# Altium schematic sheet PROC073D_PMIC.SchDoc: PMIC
size 431 x 279 mm; Date: Not shown in title block; ApprovedBy: Not shown in title block; CheckedBy: Not shown in title block; Author: Not shown in title block; CompanyName: Not shown in title block; DrawnBy: Charles F. Oladimeji; Engineer: Not shown in title block; Organization: Not shown in title block; Address1: Not shown in title block; Address2: Not shown in title block; Address3: Not shown in title block; Address4: Not shown in title block; DocumentNumber: 3; Revision: Use project parameter SCH_Rev; SheetNumber: 3; SheetTotal: 13; PageSetup: Record=PageOptions¦CenterHorizontal=True¦CenterVertical=True¦PrintScale=1.00¦XCorrection=1.00¦YCorrection=1.00¦PrintKind=0¦BorderSize=5000000¦LeftOffset=0¦BottomOffset=0¦Orientation=2¦PaperLength=1000¦PaperWidth=1000¦Scale=100¦PaperSource=15¦PrintQuality=600¦MediaType=1¦DitherType=10¦PaperKind=Letter¦PrintScaleMode=1
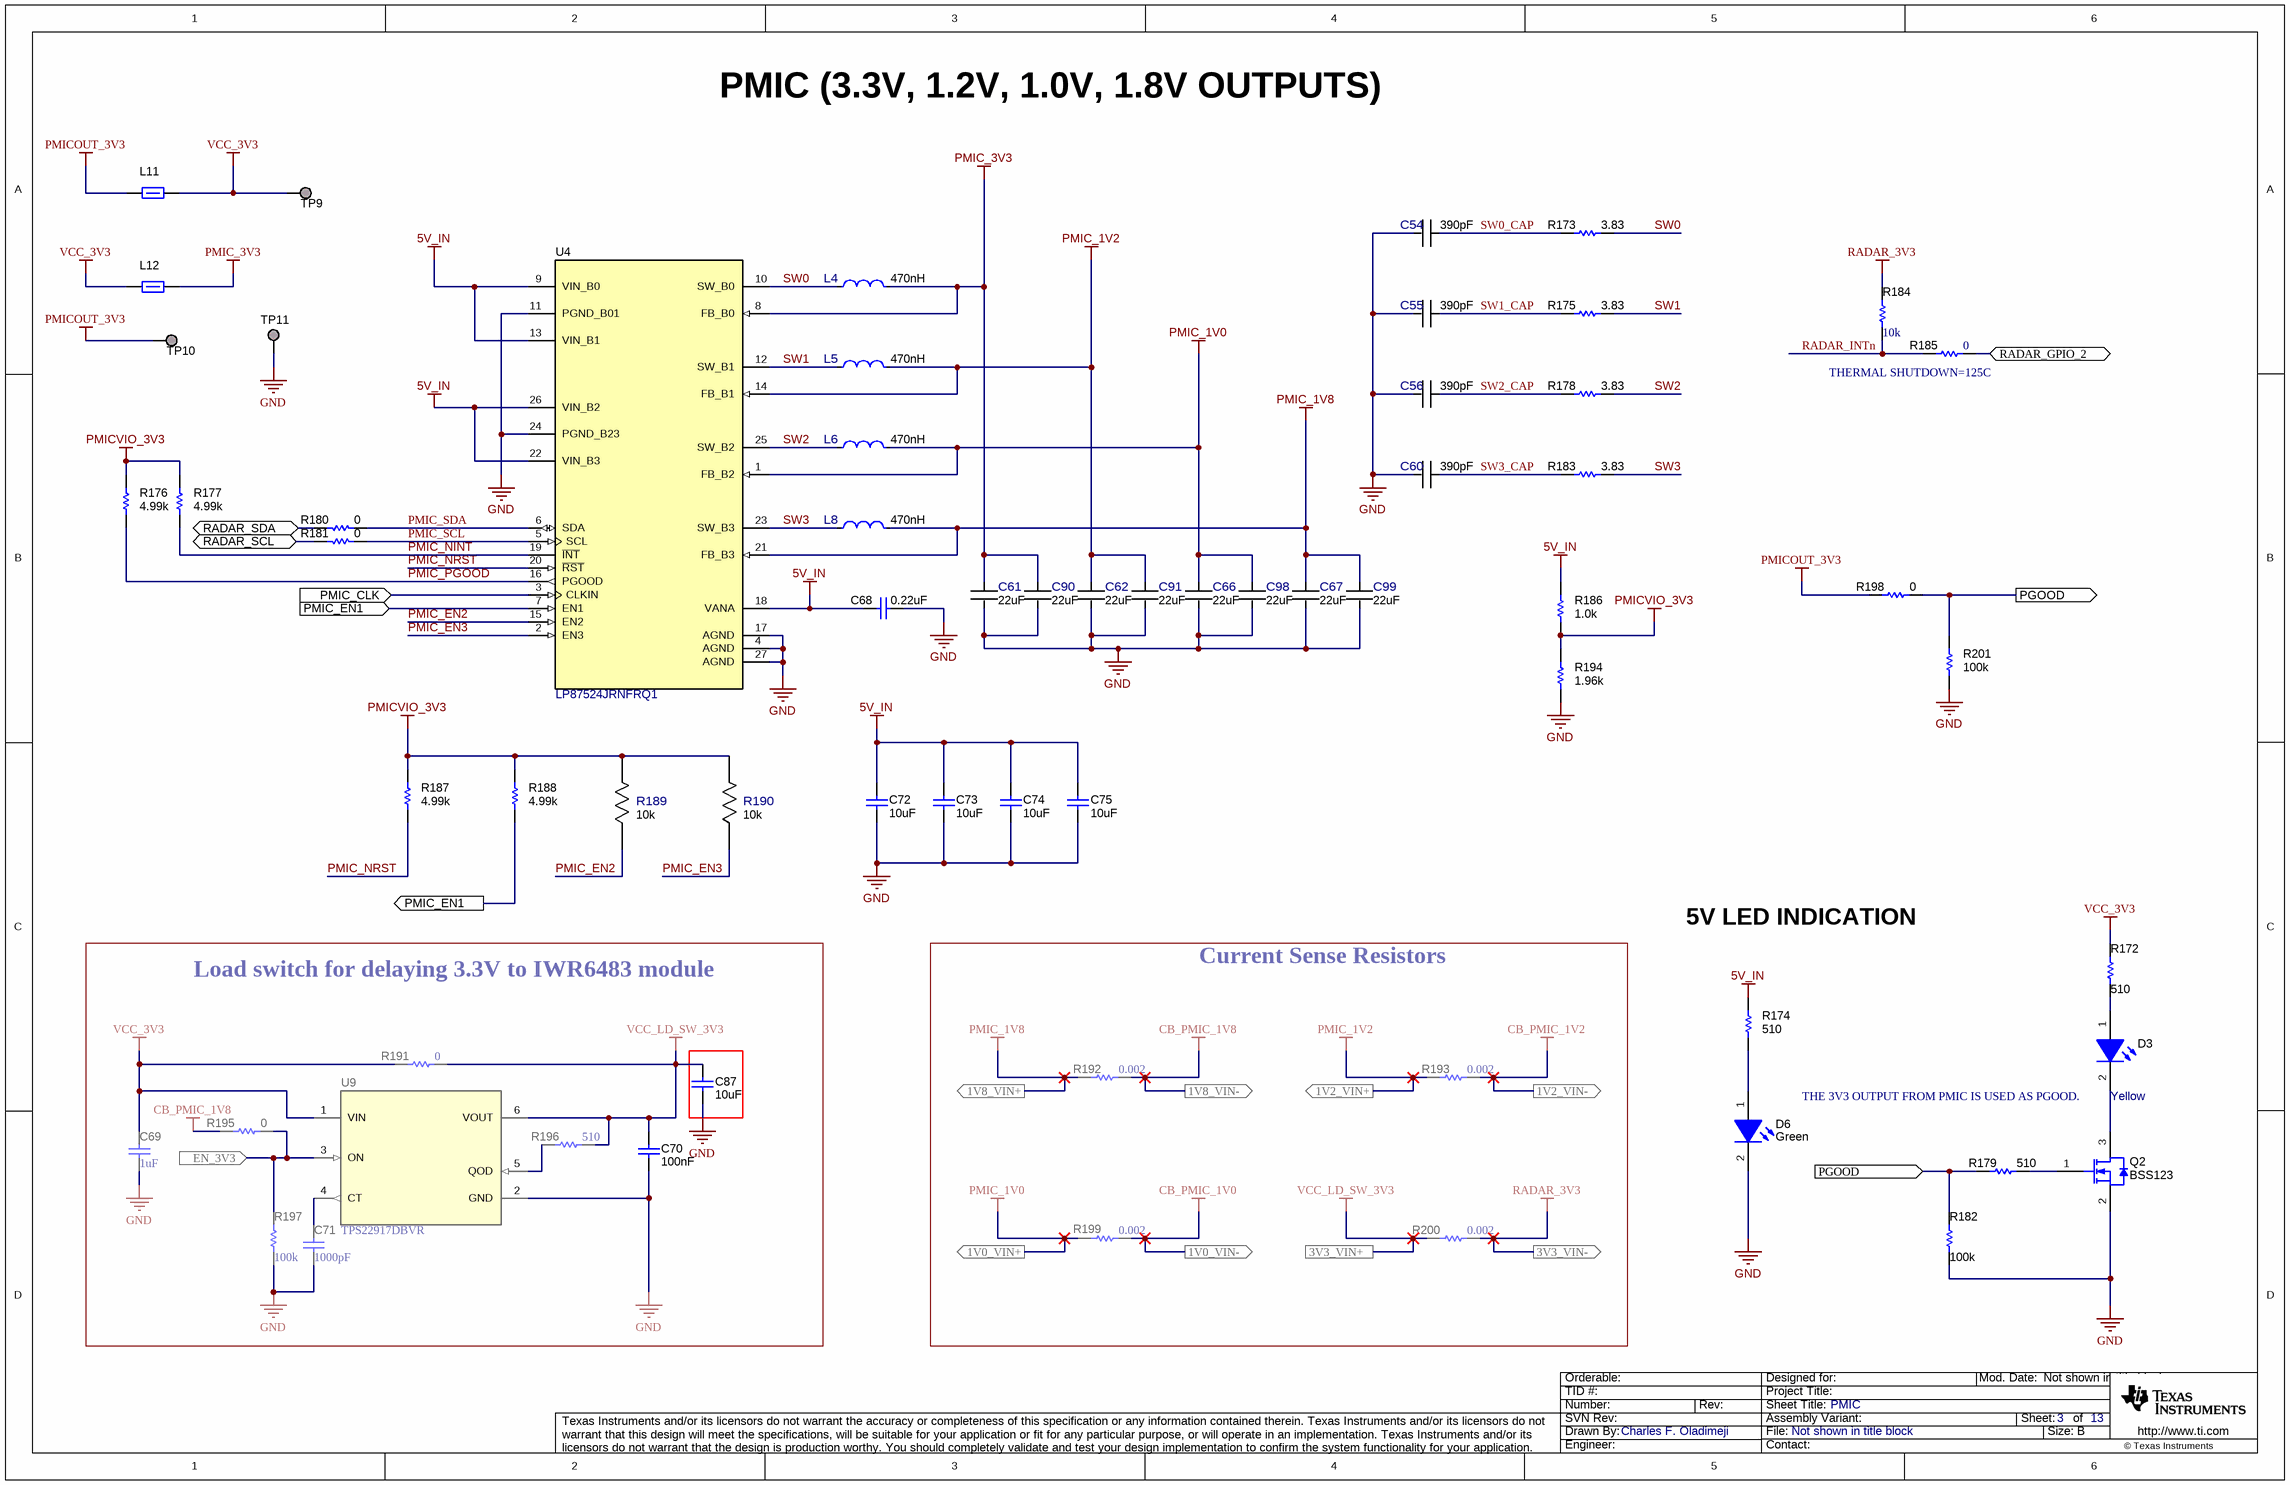
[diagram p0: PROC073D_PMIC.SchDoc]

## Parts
C54  Cap_F: 390pF  [FP-TMK063CG391JT-F_0201 (0603 Metric)-IPC_C]  (hidden comment: TMK063CG391JT-F)
C55  Cap_F: 390pF  [FP-TMK063CG391JT-F_0201 (0603 Metric)-IPC_C]  (hidden comment: TMK063CG391JT-F)
C56  Cap_F: 390pF  [FP-TMK063CG391JT-F_0201 (0603 Metric)-IPC_C]  (hidden comment: TMK063CG391JT-F)
C60  Cap_F: 390pF  [FP-TMK063CG391JT-F_0201 (0603 Metric)-IPC_C]  (hidden comment: TMK063CG391JT-F)
C61  Cap_F: 22uF  [FP-CL05A226MQ5N6J8_0402 (1005 Metric)-IPC_C]  (hidden comment: CL05A226MQ5N6J8)
C62  Cap_F: 22uF  [FP-CL05A226MQ5N6J8_0402 (1005 Metric)-IPC_C]  (hidden comment: CL05A226MQ5N6J8)
C66  Cap_F: 22uF  [FP-CL05A226MQ5N6J8_0402 (1005 Metric)-IPC_C]  (hidden comment: CL05A226MQ5N6J8)
C67  Cap_F: 22uF  [FP-CL05A226MQ5N6J8_0402 (1005 Metric)-IPC_C]  (hidden comment: CL05A226MQ5N6J8)
C68  value 0.22uF  [0201_033L]  (hidden comment: LMK063BJ224MP-F)
C69  ValueDisplayed: 1uF  [0603]  (hidden comment: CL10B105KQ8NNNC)
C70  Cap_F: 100nF  [0603]  (hidden comment: C0603C104J5RACTU)
C71  ValueDisplayed: 1000pF  [0402]  (hidden comment: CGA2B3X7S2A102K050BB)
C72  value 10uF  [0402_070]  (hidden comment: CL05A106MP5NUNC)
C73  value 10uF  [0402_070]  (hidden comment: CL05A106MP5NUNC)
C74  value 10uF  [0402_070]  (hidden comment: CL05A106MP5NUNC)
C75  value 10uF  [0402_070]  (hidden comment: CL05A106MP5NUNC)
C87  ValueDisplayed: 10uF  [0603S]  (hidden comment: GRT188R61A106KE13D)
C90  Cap_F: 22uF  [FP-CL05A226MQ5N6J8_0402 (1005 Metric)-IPC_C]  (hidden comment: CL05A226MQ5N6J8)
C91  Cap_F: 22uF  [FP-CL05A226MQ5N6J8_0402 (1005 Metric)-IPC_C]  (hidden comment: CL05A226MQ5N6J8)
C98  Cap_F: 22uF  [FP-CL05A226MQ5N6J8_0402 (1005 Metric)-IPC_C]  (hidden comment: CL05A226MQ5N6J8)
C99  Cap_F: 22uF  [FP-CL05A226MQ5N6J8_0402 (1005 Metric)-IPC_C]  (hidden comment: CL05A226MQ5N6J8)
D3  value Yellow  [TLMx1000_Yellow]  (hidden comment: TLMY1000-GS08)
D6  Color: Green  [APHHS1005_Green]  (hidden comment: APHHS1005CGCK)
L4  Ind_H: 470nH  [FP-MCKK2012TR47M_0805 (2012 Metric)-IPC_C]  (hidden comment: MCKK2012TR47M)
L5  Ind_H: 470nH  [FP-MCKK2012TR47M_0805 (2012 Metric)-IPC_C]  (hidden comment: MCKK2012TR47M)
L6  Ind_H: 470nH  [FP-MCKK2012TR47M_0805 (2012 Metric)-IPC_C]  (hidden comment: MCKK2012TR47M)
L8  Ind_H: 470nH  [FP-MCKK2012TR47M_0805 (2012 Metric)-IPC_C]  (hidden comment: MCKK2012TR47M)
L11  BLM15PD300SZ1D  [0402L]  (value not drawn)
L12  BLM15PD300SZ1D  [0402L]  (value not drawn)
Q2  BSS123  [SOT-23]
R172  ValueDisplayed: 510  [0402L]  (hidden comment: ERJ-2GEJ511X)
R173  Res_ohm: 3.83  [FP-RC0402FR-073R83L_0402 (1005 Metric)-IPC_C]  (hidden comment: RC0402FR-073R83L)
R174  value 510  [0201L]  (hidden comment: RC0201JR-07510RL)
R175  Res_ohm: 3.83  [FP-RC0402FR-073R83L_0402 (1005 Metric)-IPC_C]  (hidden comment: RC0402FR-073R83L)
R176  value 4.99k  [0201L]  (hidden comment: RC0201FR-074K99L)
R177  value 4.99k  [0201L]  (hidden comment: RC0201FR-074K99L)
R178  Res_ohm: 3.83  [FP-RC0402FR-073R83L_0402 (1005 Metric)-IPC_C]  (hidden comment: RC0402FR-073R83L)
R179  ValueDisplayed: 510  [0402L]  (hidden comment: ERJ-2GEJ511X)
R180  Res_ohm: 0  [FP-RC0201JR-070RL_0201 (0603 Metric)-MFG]  (hidden comment: RC0201JR-070RL)
R181  Res_ohm: 0  [FP-RC0201JR-070RL_0201 (0603 Metric)-MFG]  (hidden comment: RC0201JR-070RL)
R182  ValueDisplayed: 100k  [0402L]  (hidden comment: CRCW0402100KFKED)
R183  Res_ohm: 3.83  [FP-RC0402FR-073R83L_0402 (1005 Metric)-IPC_C]  (hidden comment: RC0402FR-073R83L)
R184  value 10k  [0402]  (hidden comment: CRCW040210K0JNED)
R185  Res_ohm: 0  [0402]  (hidden comment: CRCW04020000Z0ED)
R186  value 1.0k  [0201L]  (hidden comment: RC0201JR-071KL)
R187  value 4.99k  [0201L]  (hidden comment: RC0201FR-074K99L)
R188  value 4.99k  [0201L]  (hidden comment: RC0201FR-074K99L)
R189  Res_ohm: 10k  [FP-RR0306P-103-D_0201-IPC_C]  (hidden comment: RR0306P-103-D)
R190  Res_ohm: 10k  [FP-RR0306P-103-D_0201-IPC_C]  (hidden comment: RR0306P-103-D)
R191  ValueDisplayed: 0  [0603]  (hidden comment: RCS06030000Z0EA)
R192  ValueDisplayed: 0.002  [1206]  (hidden comment: PMR18EZPFV2L00)
R193  ValueDisplayed: 0.002  [1206]  (hidden comment: PMR18EZPFV2L00)
R194  value 1.96k  [0201L]  (hidden comment: RC0201FR-071K96L)
R195  ValueDisplayed: 0  [0603]  (hidden comment: MCT06030Z0000ZP500)
R196  ValueDisplayed: 510  [0402]  (hidden comment: CRCW0402510RJNED)
R197  ValueDisplayed: 100k  [0402]  (hidden comment: ERJ-2RKF1003X)
R198  Res_ohm: 0  [FP-RC0201JR-070RL_0201 (0603 Metric)-MFG]  (hidden comment: RC0201JR-070RL)
R199  ValueDisplayed: 0.002  [1206]  (hidden comment: PMR18EZPFV2L00)
R200  ValueDisplayed: 0.002  [1206]  (hidden comment: PMR18EZPFV2L00)
R201  value 100k  [0201L]  (hidden comment: CRCW0201100KFKED)
TP9  TESTPOINT  [TP_25MIL-SMT]  (value not drawn)  (no BOM)
TP10  TESTPOINT  [TP_25MIL-SMT]  (value not drawn)  (no BOM)
TP11  TESTPOINT  [TP_VIA_060RND040]  (value not drawn)  (no BOM)
U4  LP87524JRNFRQ1  [RNF0026C]
U9  TPS22917DBVR  [DBV0006A_N]

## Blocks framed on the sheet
Load switch for delaying 3.3V to IWR6483 module: C69-C71 C87 R191 R195-R197 U9
Current Sense Resistors: R192 R193 R199 R200

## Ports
1V0_VIN+ (out), 1V0_VIN- (out), 1V2_VIN+ (out), 1V2_VIN- (out), 1V8_VIN+ (out), 1V8_VIN- (out), 3V3_VIN+, 3V3_VIN- (out), EN_3V3 (in), PGOOD (in), PGOOD (out), PMIC_CLK (in), PMIC_EN1 (in), PMIC_EN1 (out), RADAR_GPIO_2 (bidir), RADAR_SCL (bidir), RADAR_SDA (bidir)

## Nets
5V_IN: C68.1 C72.1 C73.1 C74.1 C75.1 R174.1 R186.2 U4.9(VIN_B0) U4.13(VIN_B1) U4.18(VANA) U4.22(VIN_B3) U4.26(VIN_B2)
CB_PMIC_1V0: R199.2 ; port 1V0_VIN-
CB_PMIC_1V2: R193.2 ; port 1V2_VIN-
CB_PMIC_1V8: R192.2 R195.1 ; port 1V8_VIN-
GND: C54.2 C55.2 C56.2 C60.2 C61.2 C62.2 C66.2 C67.2 C68.2 C69.2 C70.2 C71.2 C72.2 C73.2 C74.2 C75.2 C87.1 C90.2 C91.2 C98.2 C99.2 D6.2(K) Q2.2(S) R182.1 R194.1 R197.1 R201.1 TP11.1 U4.4(AGND) U4.11(PGND_B01) U4.17(AGND) U4.24(PGND_B23) U4.27(AGND) U9.2(GND)
PMIC_1V0: C66.1 C98.1 L6.1 R199.1 U4.1(FB_B2) ; port 1V0_VIN+
PMIC_1V2: C62.1 C91.1 L5.1 R193.1 U4.14(FB_B1) ; port 1V2_VIN+
PMIC_1V8: C67.1 C99.1 L8.1 R192.1 U4.21(FB_B3) ; port 1V8_VIN+
PMIC_3V3: C61.1 C90.1 L4.1 L12.2 U4.8(FB_B0)
PMICOUT_3V3: L11.1 R198.2 TP10.1
PMICVIO_3V3: R176.2 R177.2 R186.1 R187.2 R188.2 R189.2 R190.2 R194.2
RADAR_3V3: R184.2 R200.2 ; port 3V3_VIN-
VCC_3V3: C69.1 L11.2 L12.1 R172.2 R191.1 TP9.1 U9.1(VIN)
VCC_LD_SW_3V3: C70.1 C87.2 R191.2 R196.1 R200.1 U9.6(VOUT) ; port 3V3_VIN+
EN_3V3: R195.2 R197.2 U9.3(ON) ; port EN_3V3
PGOOD: R179.1 R182.2 R198.1 R201.2 ; port PGOOD
PMIC_CLK: U4.3(CLKIN) ; port PMIC_CLK
PMIC_EN1: R188.1 U4.7(EN1) ; port PMIC_EN1
PMIC_EN2: R189.1 U4.15(EN2)
PMIC_EN3: R190.1 U4.2(EN3)
PMIC_NINT: R177.1 U4.19(~{INT})
PMIC_NRST: R187.1 U4.20(~{RST})
PMIC_PGOOD: R176.1 U4.16(PGOOD)
PMIC_SCL: R181.2 U4.5(SCL)
PMIC_SDA: R180.2 U4.6(SDA)
RADAR_GPIO_2: R185.2 ; port RADAR_GPIO_2
RADAR_INTn: R184.1 R185.1
RADAR_SCL: R181.1 ; port RADAR_SCL
RADAR_SDA: R180.1 ; port RADAR_SDA
SW0: L4.2 R173.2 U4.10(SW_B0)
SW0_CAP: C54.1 R173.1
SW1: L5.2 R175.2 U4.12(SW_B1)
SW1_CAP: C55.1 R175.1
SW2: L6.2 R178.2 U4.25(SW_B2)
SW2_CAP: C56.1 R178.1
SW3: L8.2 R183.2 U4.23(SW_B3)
SW3_CAP: C60.1 R183.1
NetC71_1: C71.1 U9.4(CT)
NetD3_1: D3.1(A) R172.1
NetD3_2: D3.2(K) Q2.3(D)
NetD6_1: D6.1(A) R174.2
NetQ2_1: Q2.1(G) R179.2
NetR196_2: R196.2 U9.5(QOD)

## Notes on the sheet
- PMIC (3.3V, 1.2V, 1.0V, 1.8V OUTPUTS)
- (near R185) THERMAL SHUTDOWN=125C
- 5V LED INDICATION
- THE 3V3 OUTPUT FROM PMIC IS USED AS PGOOD.

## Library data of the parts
C54-C56 C60 = CMP-0086438-1: CAP CER 390PF 25V C0G/NP0 0201; Manufacturer: Taiyo Yuden; AEC Qualified: No; SizeZ_mm: 0.33mm; Symbol Name: SYM-TMK063CG391JT-F; TempCo: 30ppm/°C; Tolerance_%: 5%
C61 C62 C66 C67 C90 C91 C98 C99 = CMP-0086447-1: CAP CER 22UF 6.3V X5R 0402; Manufacturer: Samsung Electro-Mechanics; AEC Qualified: No; SizeZ_mm: 0.55mm; Symbol Name: SYM-CL05A226MQ5N6J8; TempCo: 15%; Tolerance_%: 20%
C68 = CMP-0009781-1: CAP, CERM, 0.22 uF, 10 V, +/- 20%, X5R, 0201; Manufacturer: Taiyo Yuden; AEC Category: Q200; AEC Qualified: N; Cap_Case: 0201; Cap_F: 220nF; SizeArea_mm2: 0.18; SizeAreaWB_mm2: 2.08; SizeX_mm: 0.6; SizeY_mm: 0.3; SizeZ_mm: 0.33; TaMax_C: 85°C; TaMin_C: -55°C; U/M: EA; Value1: Unknown; Value2: 10V
C69 = CMP-0007111-4: CAP, CERM, 1 uF, 6.3 V, +/- 10%, X7R, 0603; Manufacturer: Samsung Electro-Mechanics; TaMin_C: -55°C; Polarized: N; SizeAreaWB_mm2: 4.68; Value1: Unknown; U/M: EA; Value: 1uF; TaMax_C: 125°C; SizeZ_mm: 1; SizeX_mm: 1.6; SizeY_mm: 0.8; Value2: 6.3V; SizeArea_mm2: 1.28; CompType: Capacitor; Cap_F: 1µF; AEC Category: Q200
C70 = CMP-0006858-4: CAP, CERM, 0.1 uF, 50 V, +/- 5%, X7R, 0603; Manufacturer: Kemet; TaMin_C: -55°C; Polarized: N; SizeAreaWB_mm2: 4.68; Value1: Unknown; U/M: EA; Value: 0.1uF; TaMax_C: 125°C; SizeZ_mm: 1; SizeX_mm: 1.6; SizeY_mm: 0.8; Value2: 50V; SizeArea_mm2: 1.28; AEC Category: Q200
C71 = CMP-0006332-2: CAP, CERM, 1000 pF, 100 V, +/- 10%, X7S, AEC-Q200 Grade 1, 0402; Manufacturer: TDK; TaMin_C: -55°C; ESR_ohm: 2.71151; Polarized: N; SizeAreaWB_mm2: 3; Value1: 2.71151 ohm; U/M: EA; Value: 1000pF; TaMax_C: 125°C; SizeZ_mm: 0.6; SizeX_mm: 1; SizeY_mm: 0.5; Value2: 100V; AEC Qualified: Y; Cap_F: 1nF; IRMS_A: 2.64589dA; AEC Category: Q200
C72-C75 = CMP-0006339-4: CAP, CERM, 10 uF, 10 V, +/- 20%, X5R, 0402; Manufacturer: Samsung Electro-Mechanics; AEC Category: Q200; AEC Qualified: N; Cap_Case: 0402; Cap_F: 10µF; SizeArea_mm2: 0.5; SizeAreaWB_mm2: 3; SizeX_mm: 1; SizeZ_mm: 0.6; TaMax_C: 85°C; TaMin_C: -55°C; U/M: EA; Value1: Unknown; Value2: 10V
C87 = CMP-0007497-5: CAP, CERM, 10 uF, 10 V, +/- 10%, X5R, 0603; Manufacturer: MuRata; Polarized: N; Value: 10uF; U/M: EA; Cap_F: 10µF; Tolerance_%: 20%; Value1: Unknown; VDC_V: 10V; TempCo: X7R; TaMin_C: -55°C; TaMax_C: 125°C; Cap_Case: 0603; SizeArea_mm2: 1.28; SizeAreaWB_mm2: 4.68; SizeX_mm: 1.6; SizeY_mm: 0.8; SizeZ_mm: 1; AEC Category: Q200
D3 = CMP-0078196-2: LED, Yellow, SMD; Manufacturer: Vishay-Semiconductor; Tjmax_C: 120°C; SizeAreaWB_mm2: 4.68; Vr_V: 6V; Power_TotalModule: 40mW; Angle: 160; SizeArea_mm2: 1.28; Ir_A: 10µA; SizeZ_mm: 0.65; Io_A: 2mA; Vf_V: 1.8V; SizeY_mm: 0.8; Value1: .04W; SizeX_mm: 1.6; Type: AlInGaP
D6 = CMP-0067682-2: LED, Green, SMD; Manufacturer: Kingbright; Angle: 120.0; Power_TotalModule: 75mW; SizeZ_mm: 0.6; Vf_V: 2.1V; Vr_V: 5V; Io_A: 20mA; Ir_A: 10µA; SizeArea_mm2: 0.5; SizeAreaWB_mm2: 3.0; SizeX_mm: 1.0; Tjmax_C: 85°C; Value1: 0.075W
L4-L6 L8 = CMP-0087178-1: FIXED IND 470NH 4.5A 39 MOHM SMD; Manufacturer: Taiyo Yuden; AEC Qualified: No; DCR_ohm: 0.032; Irms: 3.1A; Material: Metal; SizeZ_mm: 1mm; Symbol Name: SYM-MCKK2012TR47M
L11 L12 = CMP-0078934-1: Inductor, Ferrite Bead, Ferrite, 2.2 A, 0.035 ohm, AEC-Q200 Grade 1, SMD; Manufacturer: MuRata; AEC Category: Q200; AEC Grade: 1; AEC Qualified: Y; DCR_ohm: 0.035; Imax_A: 2.2A; SizeArea_mm2: 0.5; SizeAreaWB_mm2: 3; SizeZ_mm: 0.6
Q2 = CMP-0000947-2: MOSFET, N-CH, 100 V, 0.17 A, SOT-23; Alternate Manufacturer: None; Manufacturer: Fairchild Semiconductor; SizeZ_mm: 1.1; ChType: N; Value2: 1.8 nC; Value1: 1; VdsMax_V: 100V; SizeX_mm: 2.5; SizeY_mm: 3; Vgs_V: 20V; Value: 100V; Rdson45_ohm: 10; SizeArea_mm2: 7.5; AEC Category: Q101; IdsMax_A: 1.7dA; SizeAreaWB_mm2: 14; U/M: EA; QgTyp_nC: 1.8
R172 R179 = CMP-0078212-1: RES, 510, 5%, 0.1 W, AEC-Q200 Grade 0, 0402; Manufacturer: Panasonic; Value_Code: 510R; SizeArea_mm2: 0.5; AEC Qualified: Y; AEC Category: Q200; Value: 510; SizeZ_mm: 0.6; EIA_Code: E24; TempCo: 200 ppm/C; AEC Grade: 0; Power_W: 100mW; VDC_V: 50V; Value2: 0.1W; U/M: EA; SizeX_mm: 1
R173 R175 R178 R183 = CMP-0086444-2: RES Thick Film SMD 3.83Ω 1% 1/16W 0402 200ppm/°C; Manufacturer: Yageo; AEC Qualified: No; Power_W: 63mW; VDC_V: 50V; SizeZ_mm: 0.4mm
R174 = CMP-0027137-1: RES, 510, 5%, 0.05 W, 0201; Manufacturer: Yageo America; AEC Category: Q200; AEC Qualified: N; EIA_Code: E24; Power_W: 50mW; SizeArea_mm2: 0.18; SizeX_mm: 0.6; SizeY_mm: 0.3; SizeZ_mm: 0.26; TempCo: 200 ppm/C; U/M: EA; Value2: 0.05W; Value_Code: 510R; VDC_V: 25V
R176 R177 R187 R188 = CMP-0027745-1: RES, 4.99 k, 1%, 0.05 W, 0201; Manufacturer: Yageo America; AEC Category: Q200; AEC Qualified: N; EIA_Code: E96; Power_W: 50mW; SizeArea_mm2: 0.18; SizeX_mm: 0.6; SizeY_mm: 0.3; SizeZ_mm: 0.26; TempCo: 200 ppm/C; U/M: EA; Value2: 0.05W; Value_Code: 4k99; VDC_V: 25V
R180 R181 R198 = CMP-0086442-2: RES SMD 0 OHM JUMPER 1/20W 0201; Manufacturer: Yageo; AEC Qualified: No; Power_W: 50mW; SizeZ_mm: 0.26mm; TempCo: 200ppm/°C; Tolerance_%: 5%; VDC_V: 25V
R182 = CMP-0025950-3: RES, 100 k, 1%, 0.063 W, AEC-Q200 Grade 0, 0402; Manufacturer: Vishay-Dale; Power_W: 63mW; TempCo: 100 ppm/C; Value: 100k; EIA_Code: E96; SizeX_mm: 1; SizeY_mm: 0.5; SizeZ_mm: 0.6; Value2: 0.063W; AEC Qualified: Y; VDC_V: 50V; AEC Category: Q200; AEC Grade: 0
R184 = CMP-0026825-5: RES, 10 k, 5%, 0.063 W, AEC-Q200 Grade 0, 0402; Manufacturer: Vishay-Dale; Power_W: 63mW; TempCo: 200 ppm/C; Value_Code: 10k0; EIA_Code: E24; SizeX_mm: 1; SizeY_mm: 0.5; SizeZ_mm: 0.6; Value2: 0.063W; CompType: Resistor; AEC Qualified: Y; VDC_V: 50V; AEC Category: Q200; AEC Grade: 0
R185 = CMP-0026822-3: RES, 0, 5%, 0.063 W, AEC-Q200 Grade 0, 0402; Manufacturer: Vishay-Dale; Power_W: 63mW; TempCo: 200 ppm/C; Value_Code: 0000; Value: 0; EIA_Code: E24; SizeX_mm: 1; SizeY_mm: 0.5; SizeZ_mm: 0.6; Value2: 0.063W; CompType: Resistor; AEC Qualified: Y; VDC_V: 50V; AEC Category: Q200
R186 = CMP-0027052-1: RES, 1.0 k, 5%, 0.05 W, 0201; Manufacturer: Yageo America; AEC Category: Q200; AEC Qualified: N; EIA_Code: E24; Power_W: 50mW; Res_ohm: 1k; SizeArea_mm2: 0.18; SizeX_mm: 0.6; SizeY_mm: 0.3; SizeZ_mm: 0.26; TempCo: 200 ppm/C; U/M: EA; Value2: 0.05W; Value_Code: 1k00; VDC_V: 25V
R189 R190 = CMP-0088002-1: 10 kOhms ±0.5% 0.05W, 1/20W Chip Resistor 0201 (0603 Metric)  Thin Film; Manufacturer: Susumu; AEC Qualified: No; Power_W: 50mW; SizeZ_mm: 0.26mm; Symbol Name: SYM-RR0306P-103-D; TempCo: 25ppm/°C; VDC_V: 15V
R191 = CMP-0081973-1: RES, 0, 0%, 0.25 W, AEC-Q200 Grade 0, 0603; Manufacturer: Vishay-Dale; SizeAreaWB_mm2: 4.68; SizeArea_mm2: 1.28; AEC Qualified: Y; AEC Category: Q200; Value: 0; SizeZ_mm: 1; SizeY_mm: 0.8; Power_W: 250mW; Value2: 0.25W; CompType: Resistor; SizeX_mm: 1.6; INSTALLATION: DNP
R192 R193 R199 R200 = CMP-0081623-1: RES, 0.002, 1%, 1 W, AEC-Q200 Grade 0, 1206; Manufacturer: Rohm; Value_Code: 2L000; SizeAreaWB_mm2: 10.92; SizeArea_mm2: 5.12; AEC Qualified: Y; AEC Category: Q200; Res_ohm: 2m; Value: 0.002; SizeZ_mm: 1.35; Green_REACh: Incomplete; TempCo: 100 ppm/C; AEC Grade: 0; Power_W: 1W; SizeY_mm: 1.6; Green_Lifecycle: Active; SizeX_mm: 3.2
R194 = CMP-0027452-1: RES, 1.96 k, 1%, 0.05 W, 0201; Manufacturer: Yageo America; AEC Category: Q200; AEC Qualified: N; EIA_Code: E96; Power_W: 50mW; SizeArea_mm2: 0.18; SizeX_mm: 0.6; SizeY_mm: 0.3; SizeZ_mm: 0.26; TempCo: 200 ppm/C; U/M: EA; Value2: 0.05W; Value_Code: 1k96; VDC_V: 25V
R195 = CMP-0025884-3: RES, 0, 5%, 0.125 W, 0603; Manufacturer: Vishay/Beyschlag; Power_W: 125mW; TempCo: ppm/C; Value_Code: 0000; U/M: EA; Value: 0; EIA_Code: E24; SizeX_mm: 1.6; SizeY_mm: 0.8; SizeZ_mm: 1; Value2: 0.125W; SizeArea_mm2: 1.28; CompType: Resistor; AEC Qualified: N; AEC Category: Q200; INSTALATION: DNP
R196 = CMP-0026944-3: RES, 510, 5%, 0.063 W, AEC-Q200 Grade 0, 0402; Manufacturer: Vishay-Dale; Power_W: 63mW; TempCo: 200 ppm/C; Value_Code: 510R; Value: 510; EIA_Code: E24; SizeX_mm: 1; SizeY_mm: 0.5; SizeZ_mm: 0.6; Value2: 0.063W; AEC Qualified: Y; VDC_V: 50V; AEC Category: Q200; AEC Grade: 0
R197 = CMP-0026659-1: RES, 100 k, 1%, 0.1 W, 0402; Manufacturer: Panasonic; Power_W: 100mW; TempCo: 100 ppm/C; U/M: EA; Value: 100k; EIA_Code: E96; SizeX_mm: 1; SizeY_mm: 0.5; SizeZ_mm: 0.6; Value2: 0.1W; VDC_V: 50V; AEC Category: Q200
R201 = CMP-0027261-3: RES, 100 k, 1%, 0.05 W, 0201; Manufacturer: Vishay-Dale; AEC Category: Q200; AEC Qualified: N; EIA_Code: E96; Power_W: 50mW; SizeArea_mm2: 0.18; SizeX_mm: 0.6; SizeY_mm: 0.3; SizeZ_mm: 0.26; TempCo: 100 ppm/C; Value2: 0.05W; VDC_V: 30V
TP9-TP11 = CMP-0078143-3: TEST POINT.  No entry in BOM.
U4 = CMP-0079120-2: 4-A + 2.5-A + Two 1.5-A Buck Converters With Integrated Switches, RNF0026C (VQFN-HR-26); Alternate PartNumber: LP87524JRNFTQ1; Alternate Manufacturer: Texas Instruments; SizeAreaWB_mm2: 27.5; SizeZ_mm: 0.9; SizeX_mm: 4; SizeY_mm: 4.5; SizeArea_mm2: 18; CompType: IC; AEC Qualified: Y; AEC Category: Q200
U9 = CMP-0077265-1: 5.5-V, 2-A, 80 mohm Low Leakage Load Switch with RCB and Programmable Rise Time, DBV0006A (SOT-23-6); Alternate PartNumber: TPS22917DBVT; Alternate Manufacturer: Texas Instruments; SizeAreaWB_mm2: 14.82; SizeZ_mm: 1.45; SizeX_mm: 2.8; SizeY_mm: 2.9; SizeArea_mm2: 8.12; CompType: IC; AEC Qualified: N; AEC Category: Q200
